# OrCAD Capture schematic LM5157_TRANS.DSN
size Custom; title: LM5157x 2.2-MHz Wide VIN Boost/Sepic/Flyback Converter with; rev: 1.0; note: Datasheet: SNVSBK7     EVM: NA; note: Synchronous Step Down Converter
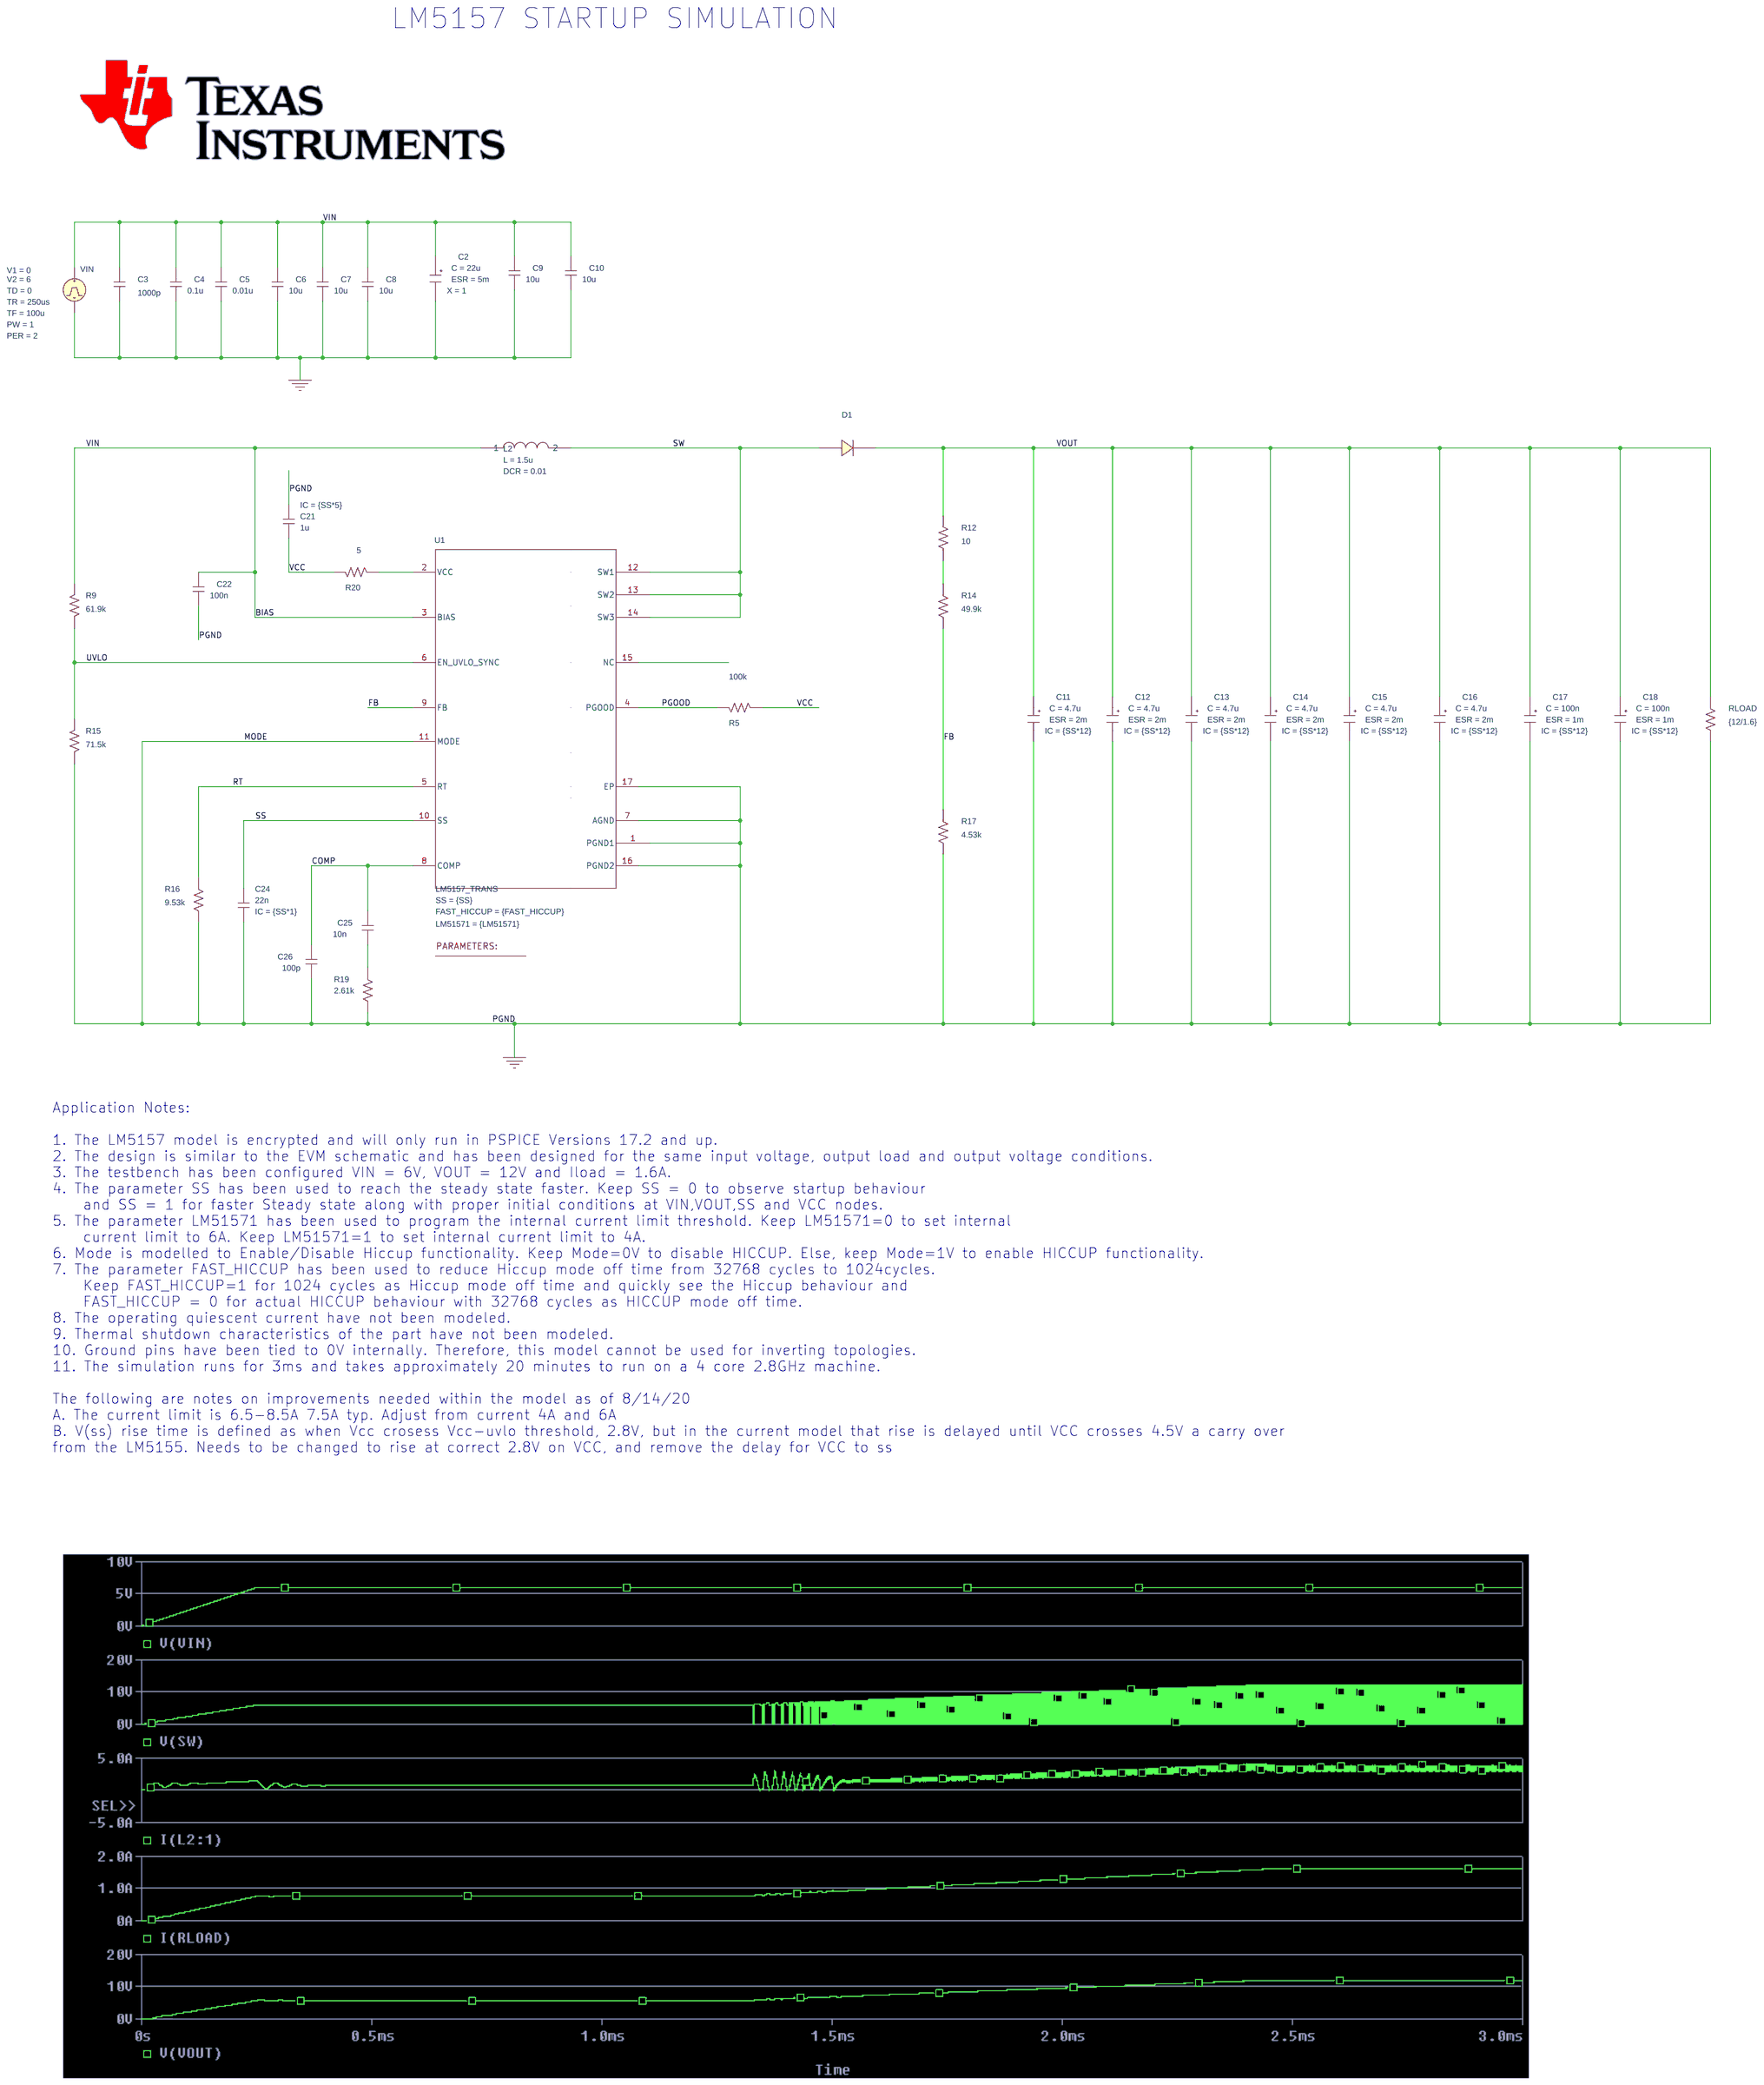
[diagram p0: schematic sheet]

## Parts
1  PARAM
C2  CESR
C3  1000p  [RAD/CK05]
C4  0.1u  [RAD/CK05]
C5  0.01u  [RAD/CK05]
C6  10u  [RAD/CK05]
C7  10u  [RAD/CK05]
C8  10u  [RAD/CK05]
C9  10u  [RAD/CK05]
C10  10u  [RAD/CK05]
C11  CESR
C12  CESR
C13  CESR
C14  CESR
C15  CESR
C16  CESR
C17  CESR
C18  CESR
C21  1u  [RAD/CK05]
C22  100n  [RAD/CK05]
C24  22n  [RAD/CK05]
C25  10n  [RAD/CK05]
C26  100p  [RAD/CK05]
D1  D_D1
L2  LDCR
R5  100k  [AX/RC05]
R9  61.9k  [AX/RC05]
R12  10  [AX/RC05]
R14  49.9k  [AX/RC05]
R15  71.5k  [AX/RC05]
R16  9.53k  [AX/RC05]
R17  4.53k  [AX/RC05]
R19  2.61k  [AX/RC05]
R20  5  [AX/RC05]
RLOAD  {12/1.6}  [AX/RC05]
U1  LM5157_TRANS  [DSS0012C]
VIN  VPULSE

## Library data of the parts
1 = PARAM: LM51571: 0; SS: 0
C2 = CESR_0: C: 22u; ESR: 5m; IC: {SS*10}; PSpiceTemplate: X^@REFDES %IN %OUT @MODEL PARAMS:  ?C|C=@C||C=100u|  ?ESR|ESR=@ESR||ESR=0.01| ?X|X=@X||X=2|  ?IC|IC=@IC||IC=2|; X: 1
C3-C10 C22 C25 C26 = C
C11-C16 = CESR_0: C: 4.7u; ESR: 2m; IC: {SS*12}; PSpiceTemplate: X^@REFDES %IN %OUT @MODEL PARAMS:  ?C|C=@C||C=100u|  ?ESR|ESR=@ESR||ESR=0.01| ?X|X=@X||X=2|  ?IC|IC=@IC||IC=2|; X: 1
C17 C18 = CESR_0: C: 100n; ESR: 1m; IC: {SS*12}; PSpiceTemplate: X^@REFDES %IN %OUT @MODEL PARAMS:  ?C|C=@C||C=100u|  ?ESR|ESR=@ESR||ESR=0.01| ?X|X=@X||X=2|  ?IC|IC=@IC||IC=2|; X: 1
C21 = C: IC: {SS*5}
C24 = C: IC: {SS*1}
D1 = D_D1
L2 = LDCR: DCR: 0.01; L: 1.5u
R5 R9 R12 R14-R17 R19 R20 RLOAD = R
U1 = LM5157_TRANS: FAST_HICCUP: {FAST_HICCUP}; LM51571: {LM51571}; SS: {SS}
VIN = VPULSE: PER: 2; PW: 1; TD: 0; TF: 100u; TR: 250us; V1: 0; V2: 6

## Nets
VCC: C21.1 R5.1 R20.2
0: C2.2(OUT) C3.2 C4.2 C5.2 C6.2 C7.2 C8.2 C9.2 C10.2 C11.2(OUT) C12.2(OUT) C13.2(OUT) C14.2(OUT) C15.2(OUT) C16.2(OUT) C17.2(OUT) C18.2(OUT) C21.2 C22.2 C24.2 C26.2 R15.1 R16.2 R17.2 R19.2 RLOAD.2 U1.1(PGND1) U1.7(AGND) U1.11(MODE) U1.16(PGND2) U1.17(EP) VIN.2(-)
BIAS: C2.1(IN) C3.1 C4.1 C5.1 C6.1 C7.1 C8.1 C9.1 C10.1 C22.1 L2.1 R9.2 U1.3(BIAS) VIN.1(+)
COMP: C25.1 C26.1 U1.8(COMP)
FB: R14.2 R17.1 U1.9(FB)
PGOOD: R5.2 U1.4(PGOOD)
RT: R16.1 U1.5(RT)
SS: C24.1 U1.10(SS)
SW: D1.2(A) L2.2 U1.12(SW1) U1.13(SW2) U1.14(SW3)
UVLO: R9.1 R15.2 U1.6(EN_UVLO_SYNC)
VOUT: C11.1(IN) C12.1(IN) C13.1(IN) C14.1(IN) C15.1(IN) C16.1(IN) C17.1(IN) C18.1(IN) D1.1(C) R12.2 RLOAD.1
N16792410: R20.1 U1.2(VCC)
N16794806: R12.1 R14.1
N16795152: C25.2 R19.1

Not connected (* = marked no-connect by the designer): U1 15(NC)

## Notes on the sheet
- LM5157 STARTUP SIMULATION
- Application Notes:
  1. The LM5157 model is encrypted and will only run in PSPICE Versions 17.2 and up.
  2. The design is similar to the EVM schematic and has been designed for the same input voltage, output load and output voltage conditions.
  3. The testbench has been configured VIN = 6V, VOUT = 12V and Iload = 1.6A.
  4. The parameter SS has been used to reach the steady state faster. Keep SS = 0 to observe startup behaviour
      and SS = 1 for faster Steady state along with proper initial conditions at VIN,VOUT,SS and VCC nodes.
  5. The parameter LM51571 has been used to program the internal current limit threshold. Keep LM51571=0 to set internal
      current limit to 6A. Keep LM51571=1 to set internal current limit to 4A.
  6. Mode is modelled to Enable/Disable Hiccup functionality. Keep Mode=0V to disable HICCUP. Else, keep Mode=1V to enable HICCUP functionality.
  7. The parameter FAST_HICCUP has been used to reduce Hiccup mode off time from 32768 cycles to 1024cycles.
      Keep FAST_HICCUP=1 for 1024 cycles as Hiccup mode off time and quickly see the Hiccup behaviour and
      FAST_HICCUP = 0 for actual HICCUP behaviour with 32768 cycles as HICCUP mode off time.
  8. The operating quiescent current have not been modeled.
  9. Thermal shutdown characteristics of the part have not been modeled.
  10. Ground pins have been tied to 0V internally. Therefore, this model cannot be used for inverting topologies.
  11. The simulation runs for 3ms and takes approximately 20 minutes to run on a 4 core 2.8GHz machine.
  The following are notes on improvements needed within the model as of 8/14/20
  A. The current limit is 6.5-8.5A 7.5A typ. Adjust from current 4A and 6A
  B. V(ss) rise time is defined as when Vcc crosess Vcc-uvlo threshold, 2.8V, but in the current model that rise is delayed until VCC crosses 4.5V a carry over
  from the LM5155. Needs to be changed to rise at correct 2.8V on VCC, and remove the delay for VCC to ss
